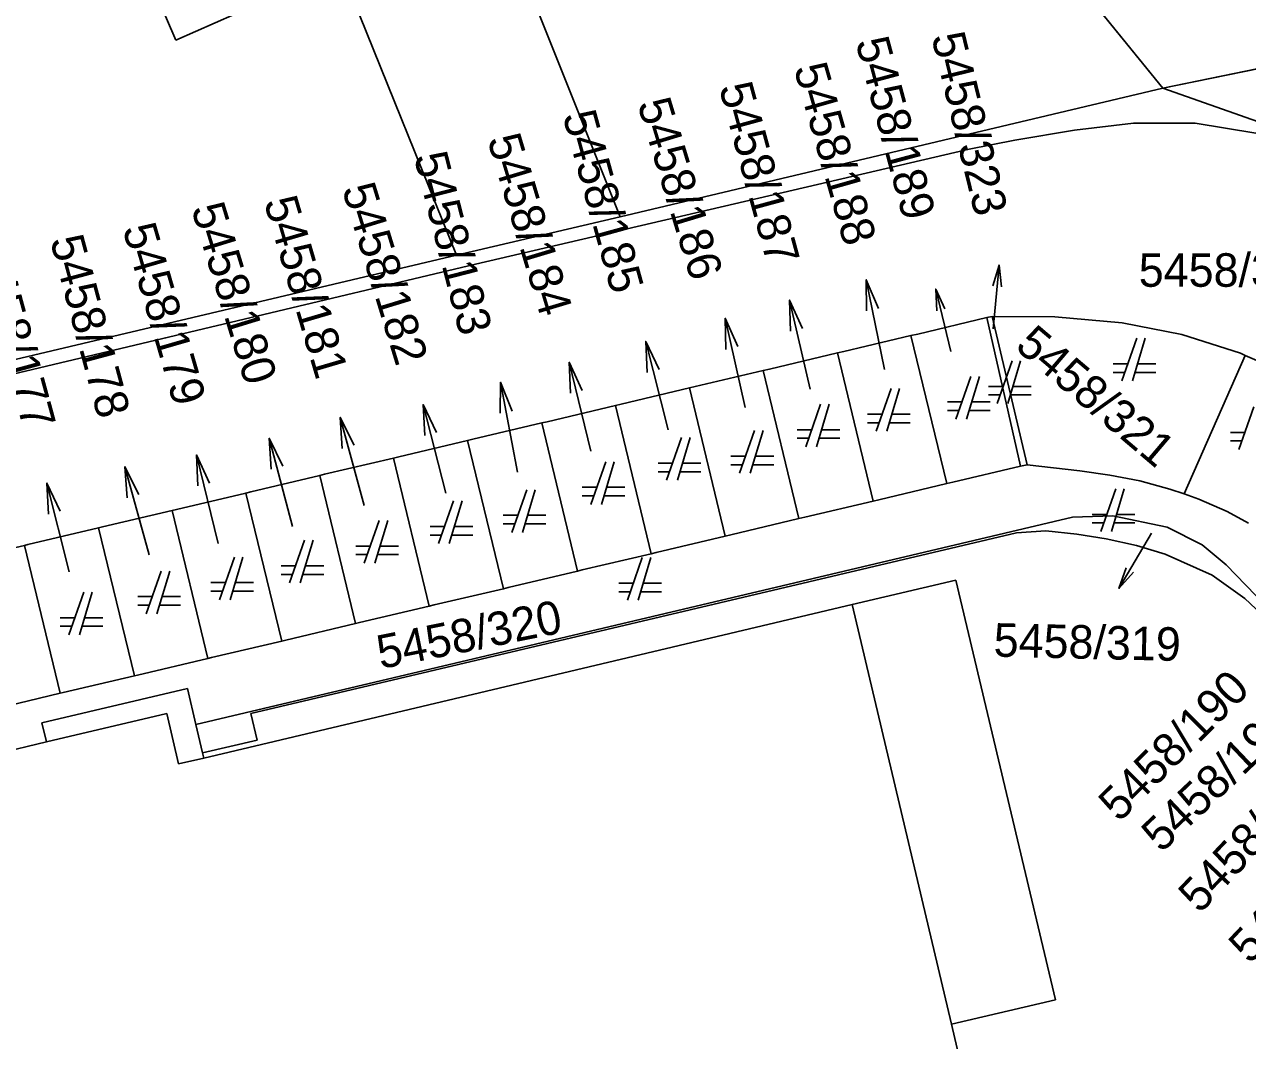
# Model space of a CAD drawing. Extents: x -263587 to -261993, y -1238795 to -1236748.
# Drawn here: x -262929.36 to -262889.25, y -1237131.15 to -1237097.8 of the extents above; entities that cross this region are included whole.
import ezdxf

# ---------------------------------------------------------------- set-up
doc = ezdxf.new("R2010")
doc.units = 0
doc.layers.add('Vrstva 1', color=7, linetype='Continuous')
doc.layers.add('Vrstva 3', color=7, linetype='Continuous')

msp = doc.modelspace()

# ---------------------------------------------------------------- linework, layer by layer
at = {"layer": 'Vrstva 1'}
for p, q in [((-262924.4, -1237098.32), (-262914.95, -1237094.13)), ((-262925.85, -1237094.91), (-262924.4, -1237098.32)), ((-262913.51, -1237094.89), (-262909.83, -1237104.11)), ((-262895.79, -1237095.25), (-262892.03, -1237099.89)), ((-262892.03, -1237099.89), (-262895.79, -1237095.25)), ((-262915.19, -1237105.37), (-262918.59, -1237096.94)), ((-262885.06, -1237098.46), (-262892.03, -1237099.89)), ((-262892.03, -1237099.89), (-262885.06, -1237098.46)), ((-262892.03, -1237099.89), (-262909.83, -1237104.11)), ((-262887.41, -1237101.52), (-262892.03, -1237099.89)), ((-262896.88, -1237101.6), (-262894.92, -1237101.27)), ((-262894.92, -1237101.27), (-262892.99, -1237101.04)), ((-262892.99, -1237101.04), (-262890.96, -1237101.04)), ((-262890.96, -1237101.04), (-262888.97, -1237101.37)), ((-262898.38, -1237101.89), (-262896.88, -1237101.6)), ((-262914.57, -1237105.67), (-262898.38, -1237101.89)), ((-262909.83, -1237104.11), (-262915.19, -1237105.37)), ((-262915.19, -1237105.37), (-263019.13, -1237129.98)), ((-262930.22, -1237109.39), (-262914.57, -1237105.67)), ((-262897.599, -1237106.383), (-262897.395, -1237105.699)), ((-262901.747, -1237107.201), (-262901.752, -1237106.181)), ((-262899.443, -1237107.202), (-262899.471, -1237106.488)), ((-262904.237, -1237107.867), (-262904.268, -1237106.848)), ((-262906.355, -1237108.463), (-262906.381, -1237107.444)), ((-262897.8, -1237107.42), (-262900.06, -1237107.96)), ((-262900.06, -1237107.96), (-262897.8, -1237107.42)), ((-262897.8, -1237107.42), (-262897.62, -1237107.38)), ((-262897.62, -1237107.38), (-262897.8, -1237107.42)), ((-262896.69, -1237112.3), (-262897.8, -1237107.42)), ((-262897.8, -1237107.42), (-262896.69, -1237112.3)), ((-262897.62, -1237107.38), (-262896.47, -1237112.25)), ((-262895.57, -1237107.4), (-262897.62, -1237107.38)), ((-262896.47, -1237112.25), (-262897.62, -1237107.38)), ((-262897.62, -1237107.38), (-262895.57, -1237107.4)), ((-262893.36, -1237107.59), (-262895.57, -1237107.4)), ((-262895.57, -1237107.4), (-262893.36, -1237107.59)), ((-262891.4, -1237107.98), (-262893.36, -1237107.59)), ((-262893.36, -1237107.59), (-262891.4, -1237107.98)), ((-262900.29, -1237108.01), (-262902.49, -1237108.53)), ((-262902.49, -1237108.53), (-262900.29, -1237108.01)), ((-262900.06, -1237107.96), (-262900.29, -1237108.01)), ((-262900.29, -1237108.01), (-262900.06, -1237107.96)), ((-262899.11, -1237112.87), (-262900.29, -1237108.01)), ((-262900.29, -1237108.01), (-262899.11, -1237112.87)), ((-262892.88, -1237108.1), (-262893.37, -1237109.5)), ((-262893.02, -1237109.5), (-262892.6, -1237108.1)), ((-262889.48, -1237108.59), (-262891.4, -1237107.98)), ((-262891.4, -1237107.98), (-262889.48, -1237108.59)), ((-262908.935, -1237109.22), (-262908.986, -1237108.202)), ((-262911.456, -1237109.904), (-262911.497, -1237108.885)), ((-262902.7, -1237108.58), (-262904.93, -1237109.11)), ((-262904.93, -1237109.11), (-262902.7, -1237108.58)), ((-262902.49, -1237108.53), (-262902.7, -1237108.58)), ((-262902.7, -1237108.58), (-262902.49, -1237108.53)), ((-262902.7, -1237108.58), (-262901.53, -1237113.45)), ((-262901.53, -1237113.45), (-262902.7, -1237108.58)), ((-262896.97, -1237108.84), (-262897.46, -1237110.24)), ((-262897.11, -1237110.24), (-262896.69, -1237108.84)), ((-262891.32, -1237113.21), (-262889.32, -1237108.66)), ((-262889.32, -1237108.66), (-262891.32, -1237113.21)), ((-262889.32, -1237108.66), (-262889.48, -1237108.59)), ((-262889.48, -1237108.59), (-262889.32, -1237108.66)), ((-262886.73, -1237109.79), (-262889.32, -1237108.66)), ((-262889.32, -1237108.66), (-262886.73, -1237109.79)), ((-262905.14, -1237109.16), (-262907.36, -1237109.68)), ((-262907.36, -1237109.68), (-262905.14, -1237109.16)), ((-262904.93, -1237109.11), (-262905.14, -1237109.16)), ((-262905.14, -1237109.16), (-262904.93, -1237109.11)), ((-262905.14, -1237109.16), (-262903.97, -1237114.02)), ((-262903.97, -1237114.02), (-262905.14, -1237109.16)), ((-262893.174, -1237108.94), (-262893.65, -1237108.94)), ((-262893.65, -1237109.22), (-262893.272, -1237109.22)), ((-262892.936, -1237109.22), (-262892.25, -1237109.22)), ((-262892.25, -1237108.94), (-262892.852, -1237108.94)), ((-262913.762, -1237110.563), (-262913.754, -1237109.543)), ((-262907.36, -1237109.68), (-262907.55, -1237109.73)), ((-262907.55, -1237109.73), (-262907.36, -1237109.68)), ((-262898.32, -1237109.35), (-262898.81, -1237110.75)), ((-262898.46, -1237110.75), (-262898.04, -1237109.35)), ((-262897.264, -1237109.68), (-262897.74, -1237109.68)), ((-262896.34, -1237109.68), (-262896.942, -1237109.68)), ((-262907.55, -1237109.73), (-262909.79, -1237110.26)), ((-262909.79, -1237110.26), (-262907.55, -1237109.73)), ((-262907.55, -1237109.73), (-262906.38, -1237114.59)), ((-262906.38, -1237114.59), (-262907.55, -1237109.73)), ((-262900.94, -1237109.75), (-262901.43, -1237111.15)), ((-262901.08, -1237111.15), (-262900.66, -1237109.75)), ((-262897.74, -1237109.96), (-262897.362, -1237109.96)), ((-262897.026, -1237109.96), (-262896.34, -1237109.96)), ((-262916.234, -1237111.294), (-262916.291, -1237110.276)), ((-262909.98, -1237110.31), (-262912.22, -1237110.84)), ((-262912.22, -1237110.84), (-262909.98, -1237110.31)), ((-262909.79, -1237110.26), (-262909.98, -1237110.31)), ((-262909.98, -1237110.31), (-262909.79, -1237110.26)), ((-262909.98, -1237110.31), (-262908.81, -1237115.17)), ((-262908.81, -1237115.17), (-262909.98, -1237110.31)), ((-262903.25, -1237110.26), (-262903.74, -1237111.66)), ((-262903.39, -1237111.66), (-262902.97, -1237110.26)), ((-262898.614, -1237110.19), (-262899.09, -1237110.19)), ((-262899.09, -1237110.47), (-262898.712, -1237110.47)), ((-262898.376, -1237110.47), (-262897.69, -1237110.47)), ((-262897.69, -1237110.19), (-262898.292, -1237110.19)), ((-262889.04, -1237110.35), (-262889.53, -1237111.75)), ((-262918.939, -1237111.713), (-262919.009, -1237110.696)), ((-262912.39, -1237110.88), (-262914.66, -1237111.41)), ((-262914.66, -1237111.41), (-262912.39, -1237110.88)), ((-262912.22, -1237110.84), (-262912.39, -1237110.88)), ((-262912.39, -1237110.88), (-262912.22, -1237110.84)), ((-262912.39, -1237110.88), (-262911.22, -1237115.74)), ((-262911.22, -1237115.74), (-262912.39, -1237110.88)), ((-262901.234, -1237110.59), (-262901.71, -1237110.59)), ((-262901.71, -1237110.87), (-262901.332, -1237110.87)), ((-262900.996, -1237110.87), (-262900.31, -1237110.87)), ((-262900.31, -1237110.59), (-262900.912, -1237110.59)), ((-262905.42, -1237111.13), (-262905.91, -1237112.53)), ((-262905.56, -1237112.53), (-262905.14, -1237111.13)), ((-262903.544, -1237111.1), (-262904.02, -1237111.1)), ((-262902.62, -1237111.1), (-262903.222, -1237111.1)), ((-262889.334, -1237111.19), (-262889.81, -1237111.19)), ((-262921.276, -1237112.398), (-262921.338, -1237111.38)), ((-262914.83, -1237111.45), (-262917.09, -1237111.99)), ((-262917.09, -1237111.99), (-262914.83, -1237111.45)), ((-262914.66, -1237111.41), (-262914.83, -1237111.45)), ((-262914.83, -1237111.45), (-262914.66, -1237111.41)), ((-262914.83, -1237111.45), (-262913.65, -1237116.32)), ((-262913.65, -1237116.32), (-262914.83, -1237111.45)), ((-262907.81, -1237111.36), (-262908.3, -1237112.76)), ((-262907.95, -1237112.76), (-262907.53, -1237111.36)), ((-262904.02, -1237111.38), (-262903.642, -1237111.38)), ((-262903.306, -1237111.38), (-262902.62, -1237111.38)), ((-262889.81, -1237111.47), (-262889.432, -1237111.47)), ((-262923.682, -1237112.946), (-262923.726, -1237111.927)), ((-262917.26, -1237112.03), (-262919.52, -1237112.56)), ((-262919.52, -1237112.56), (-262917.26, -1237112.03)), ((-262917.09, -1237111.99), (-262917.26, -1237112.03)), ((-262917.26, -1237112.03), (-262917.09, -1237111.99)), ((-262917.26, -1237112.03), (-262916.09, -1237116.89)), ((-262916.09, -1237116.89), (-262917.26, -1237112.03)), ((-262905.714, -1237111.97), (-262906.19, -1237111.97)), ((-262904.79, -1237111.97), (-262905.392, -1237111.97)), ((-262925.996, -1237113.336), (-262926.07, -1237112.319)), ((-262910.3, -1237112.15), (-262910.79, -1237113.55)), ((-262910.44, -1237113.55), (-262910.02, -1237112.15)), ((-262908.104, -1237112.2), (-262908.58, -1237112.2)), ((-262908.58, -1237112.48), (-262908.202, -1237112.48)), ((-262907.866, -1237112.48), (-262907.18, -1237112.48)), ((-262907.18, -1237112.2), (-262907.782, -1237112.2)), ((-262906.19, -1237112.25), (-262905.812, -1237112.25)), ((-262905.476, -1237112.25), (-262904.79, -1237112.25)), ((-262898.91, -1237112.82), (-262896.69, -1237112.3)), ((-262896.69, -1237112.3), (-262898.91, -1237112.82)), ((-262896.47, -1237112.25), (-262896.69, -1237112.3)), ((-262896.69, -1237112.3), (-262896.47, -1237112.25)), ((-262896.47, -1237112.25), (-262894.75, -1237112.45)), ((-262894.75, -1237112.45), (-262896.47, -1237112.25)), ((-262894.75, -1237112.45), (-262893.76, -1237112.59)), ((-262893.76, -1237112.59), (-262894.75, -1237112.45)), ((-262928.579, -1237113.868), (-262928.628, -1237112.85)), ((-262919.68, -1237112.6), (-262921.94, -1237113.14)), ((-262921.94, -1237113.14), (-262919.68, -1237112.6)), ((-262919.52, -1237112.56), (-262919.68, -1237112.6)), ((-262919.68, -1237112.6), (-262919.52, -1237112.56)), ((-262919.68, -1237112.6), (-262918.51, -1237117.46)), ((-262918.51, -1237117.46), (-262919.68, -1237112.6)), ((-262901.34, -1237113.4), (-262899.11, -1237112.87)), ((-262899.11, -1237112.87), (-262901.34, -1237113.4)), ((-262899.11, -1237112.87), (-262898.91, -1237112.82)), ((-262898.91, -1237112.82), (-262899.11, -1237112.87)), ((-262893.76, -1237112.59), (-262892.78, -1237112.78)), ((-262892.78, -1237112.78), (-262893.76, -1237112.59)), ((-262892.78, -1237112.78), (-262891.79, -1237113.05)), ((-262891.79, -1237113.05), (-262892.78, -1237112.78)), ((-262922.1, -1237113.18), (-262924.38, -1237113.72)), ((-262924.38, -1237113.72), (-262922.1, -1237113.18)), ((-262921.94, -1237113.14), (-262922.1, -1237113.18)), ((-262922.1, -1237113.18), (-262921.94, -1237113.14)), ((-262922.1, -1237113.18), (-262920.92, -1237118.04)), ((-262920.92, -1237118.04), (-262922.1, -1237113.18)), ((-262912.89, -1237113.07), (-262913.38, -1237114.47)), ((-262913.03, -1237114.47), (-262912.61, -1237113.07)), ((-262910.594, -1237112.99), (-262911.07, -1237112.99)), ((-262911.07, -1237113.27), (-262910.692, -1237113.27)), ((-262910.356, -1237113.27), (-262909.67, -1237113.27)), ((-262909.67, -1237112.99), (-262910.272, -1237112.99)), ((-262893.57, -1237113.04), (-262894.06, -1237114.44)), ((-262893.71, -1237114.44), (-262893.29, -1237113.04)), ((-262891.79, -1237113.05), (-262891.32, -1237113.21)), ((-262891.32, -1237113.21), (-262891.79, -1237113.05)), ((-262891.32, -1237113.21), (-262890.84, -1237113.38)), ((-262890.84, -1237113.38), (-262891.32, -1237113.21)), ((-262924.38, -1237113.72), (-262924.52, -1237113.75)), ((-262924.52, -1237113.75), (-262924.38, -1237113.72)), ((-262915.29, -1237113.44), (-262915.78, -1237114.84)), ((-262915.43, -1237114.84), (-262915.01, -1237113.44)), ((-262903.77, -1237113.97), (-262901.53, -1237113.45)), ((-262901.53, -1237113.45), (-262903.77, -1237113.97)), ((-262901.53, -1237113.45), (-262901.34, -1237113.4)), ((-262901.34, -1237113.4), (-262901.53, -1237113.45)), ((-262890.84, -1237113.38), (-262889.91, -1237113.79)), ((-262889.91, -1237113.79), (-262890.84, -1237113.38)), ((-262924.52, -1237113.75), (-262926.81, -1237114.29)), ((-262926.81, -1237114.29), (-262924.52, -1237113.75)), ((-262924.52, -1237113.75), (-262923.35, -1237118.61)), ((-262923.35, -1237118.61), (-262924.52, -1237113.75)), ((-262894.99, -1237113.97), (-262923.74, -1237120.78)), ((-262923.74, -1237120.78), (-262894.99, -1237113.97)), ((-262917.73, -1237114.08), (-262918.22, -1237115.48)), ((-262917.87, -1237115.48), (-262917.45, -1237114.08)), ((-262913.184, -1237113.91), (-262913.66, -1237113.91)), ((-262912.26, -1237113.91), (-262912.862, -1237113.91)), ((-262906.2, -1237114.55), (-262903.97, -1237114.02)), ((-262903.97, -1237114.02), (-262906.2, -1237114.55)), ((-262903.97, -1237114.02), (-262903.77, -1237113.97)), ((-262903.77, -1237113.97), (-262903.97, -1237114.02)), ((-262893.66, -1237113.93), (-262894.99, -1237113.97)), ((-262894.99, -1237113.97), (-262893.66, -1237113.93)), ((-262893.864, -1237113.88), (-262894.34, -1237113.88)), ((-262891.88, -1237114.3), (-262893.66, -1237113.93)), ((-262893.66, -1237113.93), (-262891.88, -1237114.3)), ((-262892.94, -1237113.88), (-262893.542, -1237113.88)), ((-262889.91, -1237113.79), (-262889.22, -1237114.17)), ((-262889.22, -1237114.17), (-262889.91, -1237113.79)), ((-262926.94, -1237114.32), (-262929.25, -1237114.87)), ((-262929.25, -1237114.87), (-262926.94, -1237114.32)), ((-262926.81, -1237114.29), (-262926.94, -1237114.32)), ((-262926.94, -1237114.32), (-262926.81, -1237114.29)), ((-262926.94, -1237114.32), (-262925.76, -1237119.18)), ((-262925.76, -1237119.18), (-262926.94, -1237114.32)), ((-262896.83, -1237114.49), (-262921.94, -1237120.41)), ((-262921.94, -1237120.41), (-262896.83, -1237114.49)), ((-262915.584, -1237114.28), (-262916.06, -1237114.28)), ((-262914.66, -1237114.28), (-262915.262, -1237114.28)), ((-262913.66, -1237114.19), (-262913.282, -1237114.19)), ((-262912.946, -1237114.19), (-262912.26, -1237114.19)), ((-262895.86, -1237114.42), (-262896.83, -1237114.49)), ((-262896.83, -1237114.49), (-262895.86, -1237114.42)), ((-262894.85, -1237114.53), (-262895.86, -1237114.42)), ((-262895.86, -1237114.42), (-262894.85, -1237114.53)), ((-262893.88, -1237114.68), (-262894.85, -1237114.53)), ((-262894.85, -1237114.53), (-262893.88, -1237114.68)), ((-262894.34, -1237114.16), (-262893.962, -1237114.16)), ((-262893.626, -1237114.16), (-262892.94, -1237114.16)), ((-262890.73, -1237114.88), (-262891.88, -1237114.3)), ((-262891.88, -1237114.3), (-262890.73, -1237114.88)), ((-262929.36, -1237114.9), (-262931.68, -1237115.44)), ((-262931.68, -1237115.44), (-262929.36, -1237114.9)), ((-262929.25, -1237114.87), (-262929.36, -1237114.9)), ((-262929.36, -1237114.9), (-262929.25, -1237114.87)), ((-262929.36, -1237114.9), (-262928.19, -1237119.75)), ((-262928.19, -1237119.75), (-262929.36, -1237114.9)), ((-262920.18, -1237114.73), (-262920.67, -1237116.13)), ((-262920.32, -1237116.13), (-262919.9, -1237114.73)), ((-262918.024, -1237114.92), (-262918.5, -1237114.92)), ((-262917.1, -1237114.92), (-262917.702, -1237114.92)), ((-262916.06, -1237114.56), (-262915.682, -1237114.56)), ((-262915.346, -1237114.56), (-262914.66, -1237114.56)), ((-262908.64, -1237115.13), (-262906.38, -1237114.59)), ((-262906.38, -1237114.59), (-262908.64, -1237115.13)), ((-262906.38, -1237114.59), (-262906.2, -1237114.55)), ((-262906.2, -1237114.55), (-262906.38, -1237114.59)), ((-262892.89, -1237114.9), (-262893.88, -1237114.68)), ((-262893.88, -1237114.68), (-262892.89, -1237114.9)), ((-262891.95, -1237115.19), (-262892.89, -1237114.9)), ((-262892.89, -1237114.9), (-262891.95, -1237115.19)), ((-262889.95, -1237115.54), (-262890.73, -1237114.88)), ((-262890.73, -1237114.88), (-262889.95, -1237115.54)), ((-262922.48, -1237115.28), (-262922.97, -1237116.68)), ((-262922.62, -1237116.68), (-262922.2, -1237115.28)), ((-262918.5, -1237115.2), (-262918.122, -1237115.2)), ((-262917.786, -1237115.2), (-262917.1, -1237115.2)), ((-262911.07, -1237115.7), (-262908.81, -1237115.17)), ((-262908.81, -1237115.17), (-262911.07, -1237115.7)), ((-262909.1, -1237115.3), (-262909.59, -1237116.7)), ((-262909.24, -1237116.7), (-262908.82, -1237115.3)), ((-262908.81, -1237115.17), (-262908.64, -1237115.13)), ((-262908.64, -1237115.13), (-262908.81, -1237115.17)), ((-262890.41, -1237115.88), (-262891.95, -1237115.19)), ((-262891.95, -1237115.19), (-262890.41, -1237115.88)), ((-262920.474, -1237115.57), (-262920.95, -1237115.57)), ((-262919.55, -1237115.57), (-262920.152, -1237115.57)), ((-262911.22, -1237115.74), (-262911.07, -1237115.7)), ((-262911.07, -1237115.7), (-262911.22, -1237115.74)), ((-262878.84, -1237127.04), (-262889.95, -1237115.54)), ((-262889.95, -1237115.54), (-262878.84, -1237127.04)), ((-262924.88, -1237115.74), (-262925.37, -1237117.14)), ((-262925.02, -1237117.14), (-262924.6, -1237115.74)), ((-262922.774, -1237116.12), (-262923.25, -1237116.12)), ((-262921.85, -1237116.12), (-262922.452, -1237116.12)), ((-262920.95, -1237115.85), (-262920.572, -1237115.85)), ((-262920.236, -1237115.85), (-262919.55, -1237115.85)), ((-262913.5, -1237116.28), (-262911.22, -1237115.74)), ((-262911.22, -1237115.74), (-262913.5, -1237116.28)), ((-262902.22, -1237116.84), (-262898.81, -1237116.04)), ((-262898.81, -1237116.04), (-262902.22, -1237116.84)), ((-262898.81, -1237116.04), (-262895.55, -1237129.81)), ((-262895.55, -1237129.81), (-262898.81, -1237116.04)), ((-262892.988, -1237115.778), (-262893.463, -1237116.311)), ((-262889.34, -1237116.64), (-262890.41, -1237115.88)), ((-262890.41, -1237115.88), (-262889.34, -1237116.64)), ((-262927.42, -1237116.43), (-262927.91, -1237117.83)), ((-262927.56, -1237117.83), (-262927.14, -1237116.43)), ((-262923.25, -1237116.4), (-262922.872, -1237116.4)), ((-262922.536, -1237116.4), (-262921.85, -1237116.4)), ((-262915.93, -1237116.85), (-262913.65, -1237116.32)), ((-262913.65, -1237116.32), (-262915.93, -1237116.85)), ((-262913.65, -1237116.32), (-262913.5, -1237116.28)), ((-262913.5, -1237116.28), (-262913.65, -1237116.32)), ((-262909.394, -1237116.14), (-262909.87, -1237116.14)), ((-262909.87, -1237116.42), (-262909.492, -1237116.42)), ((-262909.156, -1237116.42), (-262908.47, -1237116.42)), ((-262908.47, -1237116.14), (-262909.072, -1237116.14)), ((-262925.174, -1237116.58), (-262925.65, -1237116.58)), ((-262925.65, -1237116.86), (-262925.272, -1237116.86)), ((-262924.936, -1237116.86), (-262924.25, -1237116.86)), ((-262924.25, -1237116.58), (-262924.852, -1237116.58)), ((-262923.48, -1237121.88), (-262902.22, -1237116.84)), ((-262902.22, -1237116.84), (-262923.48, -1237121.88)), ((-262918.37, -1237117.43), (-262916.09, -1237116.89)), ((-262916.09, -1237116.89), (-262918.37, -1237117.43)), ((-262916.09, -1237116.89), (-262915.93, -1237116.85)), ((-262915.93, -1237116.85), (-262916.09, -1237116.89)), ((-262898.96, -1237130.61), (-262902.22, -1237116.84)), ((-262888.61, -1237117.32), (-262889.34, -1237116.64)), ((-262889.34, -1237116.64), (-262888.61, -1237117.32)), ((-262927.714, -1237117.27), (-262928.19, -1237117.27)), ((-262926.79, -1237117.27), (-262927.392, -1237117.27)), ((-262928.19, -1237117.55), (-262927.812, -1237117.55)), ((-262927.476, -1237117.55), (-262926.79, -1237117.55)), ((-262920.79, -1237118.01), (-262918.51, -1237117.46)), ((-262918.51, -1237117.46), (-262920.79, -1237118.01)), ((-262918.51, -1237117.46), (-262918.37, -1237117.43)), ((-262918.37, -1237117.43), (-262918.51, -1237117.46)), ((-262923.23, -1237118.58), (-262920.92, -1237118.04)), ((-262920.92, -1237118.04), (-262923.23, -1237118.58)), ((-262920.92, -1237118.04), (-262920.79, -1237118.01)), ((-262920.79, -1237118.01), (-262920.92, -1237118.04)), ((-262925.66, -1237119.16), (-262923.35, -1237118.61)), ((-262923.35, -1237118.61), (-262925.66, -1237119.16)), ((-262923.35, -1237118.61), (-262923.23, -1237118.58)), ((-262923.23, -1237118.58), (-262923.35, -1237118.61)), ((-262928.1, -1237119.73), (-262925.76, -1237119.18)), ((-262925.76, -1237119.18), (-262928.1, -1237119.73)), ((-262925.76, -1237119.18), (-262925.66, -1237119.16)), ((-262925.66, -1237119.16), (-262925.76, -1237119.18)), ((-262928.79, -1237120.72), (-262924.02, -1237119.59)), ((-262924.02, -1237119.59), (-262928.79, -1237120.72)), ((-262928.19, -1237119.75), (-262928.1, -1237119.73)), ((-262928.1, -1237119.73), (-262928.19, -1237119.75)), ((-262924.02, -1237119.59), (-262923.74, -1237120.78)), ((-262923.74, -1237120.78), (-262924.02, -1237119.59)), ((-262930.53, -1237120.31), (-262928.19, -1237119.75)), ((-262928.19, -1237119.75), (-262930.53, -1237120.31)), ((-262928.64, -1237121.35), (-262924.7, -1237120.42)), ((-262924.7, -1237120.42), (-262924.31, -1237122.07)), ((-262921.94, -1237120.41), (-262921.73, -1237121.29)), ((-262921.73, -1237121.29), (-262921.94, -1237120.41)), ((-262928.64, -1237121.35), (-262928.79, -1237120.72)), ((-262928.79, -1237120.72), (-262928.64, -1237121.35)), ((-262923.74, -1237120.78), (-262923.52, -1237121.71)), ((-262923.52, -1237121.71), (-262923.74, -1237120.78)), ((-262931.9, -1237122.12), (-262928.64, -1237121.35)), ((-262928.64, -1237121.35), (-262931.9, -1237122.12)), ((-262921.73, -1237121.29), (-262923.52, -1237121.71)), ((-262923.52, -1237121.71), (-262921.73, -1237121.29)), ((-262923.52, -1237121.71), (-262923.48, -1237121.88)), ((-262923.48, -1237121.88), (-262923.52, -1237121.71)), ((-262924.31, -1237122.07), (-262923.48, -1237121.88)), ((-262895.55, -1237129.81), (-262898.96, -1237130.61)), ((-262898.96, -1237130.61), (-262895.55, -1237129.81)), ((-262898.96, -1237130.61), (-262898.47, -1237132.66)), ((-262898.47, -1237132.66), (-262898.96, -1237130.61))]:
    msp.add_line(p, q, dxfattribs=at)
for points in [[(-262897.59, -1237107.79), (-262897.395, -1237105.699), (-262897.32, -1237106.409)], [(-262901.15, -1237109.12), (-262901.752, -1237106.181), (-262901.355, -1237107.121)], [(-262898.98, -1237108.53), (-262899.471, -1237106.488), (-262899.171, -1237107.136)], [(-262903.59, -1237109.77), (-262904.268, -1237106.848), (-262903.847, -1237107.777)], [(-262905.72, -1237110.37), (-262906.381, -1237107.444), (-262905.965, -1237108.375)], [(-262908.25, -1237111.11), (-262908.986, -1237108.202), (-262908.547, -1237109.122)], [(-262910.79, -1237111.8), (-262911.497, -1237108.885), (-262911.067, -1237109.809)], [(-262913.19, -1237112.49), (-262913.754, -1237109.543), (-262913.369, -1237110.488)], [(-262915.54, -1237113.18), (-262916.291, -1237110.276), (-262915.847, -1237111.194)], [(-262918.22, -1237113.59), (-262919.009, -1237110.696), (-262918.553, -1237111.608)], [(-262920.57, -1237114.28), (-262921.338, -1237111.38), (-262920.889, -1237112.295)], [(-262923.01, -1237114.84), (-262923.726, -1237111.927), (-262923.293, -1237112.85)], [(-262925.27, -1237115.21), (-262926.07, -1237112.319), (-262925.611, -1237113.229)], [(-262927.9, -1237115.76), (-262928.628, -1237112.85), (-262928.191, -1237113.771)], [(-262892.4, -1237114.5), (-262893.463, -1237116.311), (-262893.229, -1237115.637)]]:
    msp.add_lwpolyline(points, dxfattribs=at)
at = {"layer": 'Vrstva 3'}
msp.add_lwpolyline([(-262885.055, -1237098.456), (-262892.03, -1237099.89), (-262895.79, -1237095.25), (-262901.89, -1237088.99), (-262919.88, -1237072.48), (-262925.51, -1237068.03), (-262915.88, -1237068.48), (-262901.95, -1237079.28)], close=True, dxfattribs=at)

# ---------------------------------------------------------------- texts
at = {"layer": 'Vrstva 1'}
for s, rotation, p in [('5458/323', 283.7287, (-262899.624, -1237098.195)), ('5458/189', 285.0465, (-262902.113, -1237098.368)), ('5458/188', 285.9059, (-262904.138, -1237099.232)), ('5458/187', 285.2184, (-262906.591, -1237099.858)), ('5458/186', 286.88, (-262909.269, -1237100.398)), ('5458/185', 285.3903, (-262911.72, -1237100.784)), ('5458/184', 286.7081, (-262914.191, -1237101.571)), ('5458/183', 284.4162, (-262916.598, -1237102.131)), ('5458/182', 287.0519, (-262918.959, -1237103.193)), ('5458/180', 287.0519, (-262923.903, -1237103.838)), ('5458/181', 286.4216, (-262921.519, -1237103.615)), ('5458/179', 286.1924, (-262926.155, -1237104.498)), ('5458/178', 285.0465, (-262928.532, -1237104.872)), ('5458/177', 285.2184, (-262930.991, -1237105.248)), ('5458/321', 319.6532, (-262896.911, -1237108.423)), ('5458/320', 11.3446, (-262917.681, -1237118.958)), ('5458/319', 358.6143, (-262897.583, -1237118.545)), ('5458/190', 44.9772, (-262893.457, -1237124.011)), ('5458/191', 43.4875, (-262892.074, -1237125.013)), ('5458/192', 46.5242, (-262890.815, -1237127.012)), ('5458/193', 46.5242, (-262889.165, -1237128.672))]:
    msp.add_text(s, height=1.1, rotation=rotation, dxfattribs=at).set_placement(p)
msp.add_text('5458/343', height=1.1, dxfattribs=at).set_placement((-262892.815, -1237106.41))

doc.saveas('drawing.dxf')
